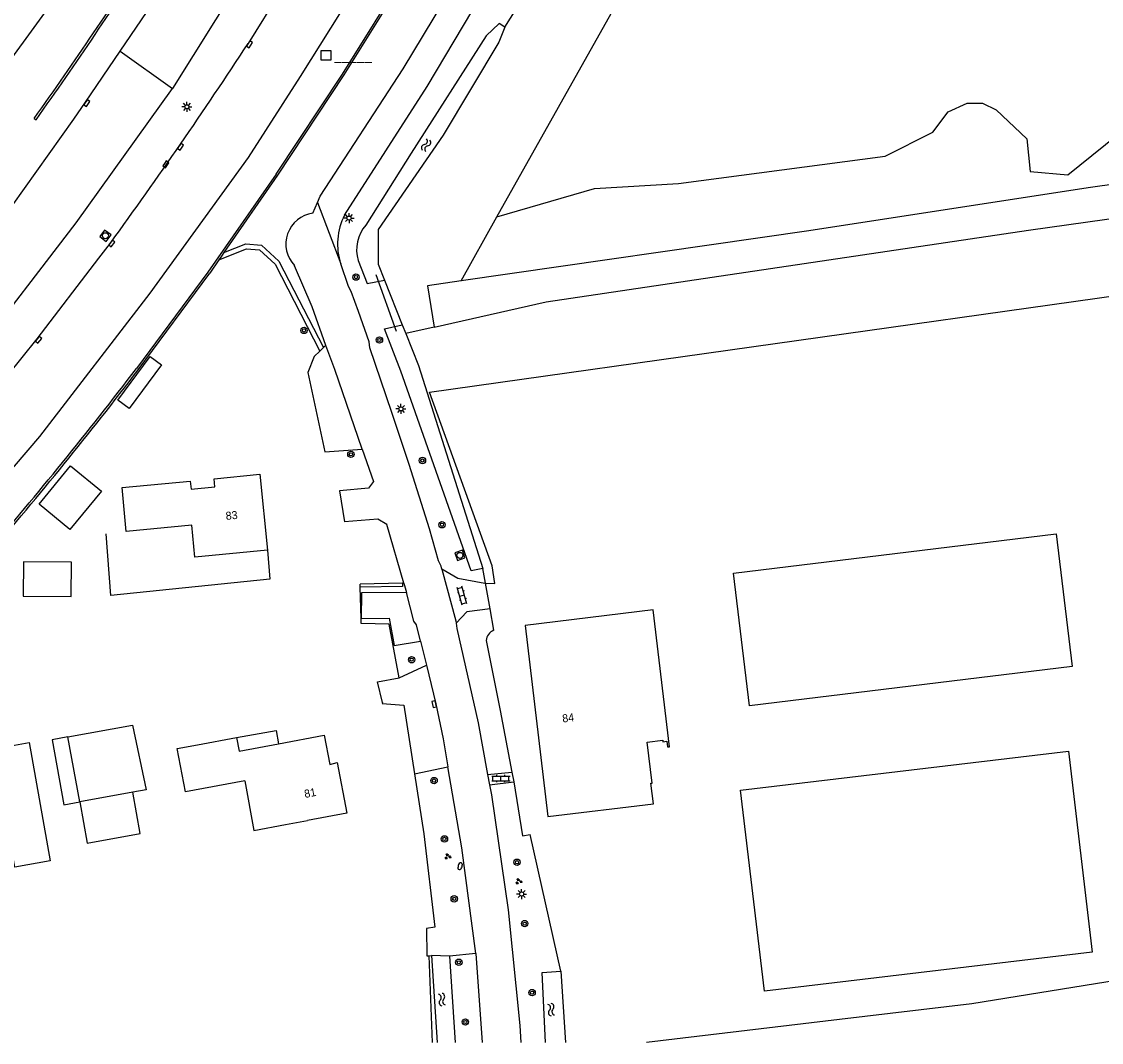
# Model space of a CAD drawing. Extents: x 125000 to 129004, y 397500 to 399008.
# Drawn here: x 125871.7 to 126006.6, y 397500 to 397627.5 of the extents above; entities that cross this region are included whole.
import ezdxf

# ---------------------------------------------------------------- set-up
doc = ezdxf.new("R2010")
doc.units = 0
for name, color, linetype in [('gg-afsc-erfafscheiding', 7, 'Continuous'), ('gg-afsc-geluidsscherm', 7, 'Continuous'), ('gg-afsc-hekwerk', 7, 'Continuous'), ('gg-anno-huisnummerreeks BGT', 7, 'Continuous'), ('gg-bbg-bijgebouw', 7, 'Continuous'), ('gg-bbg-gedigitaliseerde bebouwing', 7, 'Continuous'), ('gg-bbg-gedigitaliseerde bijgebouw', 7, 'Continuous'), ('gg-bbg-hoofdgebouw', 7, 'Continuous'), ('gg-bbg-luifel en loopbrug', 7, 'Continuous'), ('gg-knt-onverhard', 7, 'Continuous'), ('gg-knt-verharding', 7, 'Continuous'), ('gg-knt-verharding nz', 7, 'Continuous'), ('gg-kntw-bovenkant insteek waterloop', 7, 'Continuous'), ('gg-kwrk-duiker nz buis', 7, 'Continuous'), ('gg-kwrk-kunstwerk', 7, 'Continuous'), ('gt-bbg-plantopografie pand', 7, 'Continuous'), ('gt-grn-groengrens', 7, 'Continuous'), ('gt-grn-vlakafsluiter', 7, 'Continuous'), ('gt-grn-weggrens', 7, 'Continuous'), ('gt-symb-boom', 7, 'Continuous'), ('gt-symb-brandkraan', 7, 'Continuous'), ('gt-symb-groenvak', 7, 'Continuous'), ('gt-symb-hm paal', 7, 'Continuous'), ('gt-symb-klinker verharding', 7, 'Continuous'), ('gt-symb-kolk', 7, 'Continuous'), ('gt-symb-lichtmast', 7, 'Continuous'), ('gt-symb-rioolschacht', 7, 'Continuous'), ('gt-symb-watersymbool', 7, 'Continuous'), ('gx-grn-maaiveld', 7, 'Continuous')]:
    doc.layers.add(name, color=color, linetype=linetype)

# ---------------------------------------------------------------- blocks, each defined once
blk = doc.blocks.new('gt0-BOOM')
at = {"layer": 'gt-symb-boom'}
for radius in [0.4, 0.2]:
    blk.add_circle((0, 0), radius, dxfattribs=at)
blk = doc.blocks.new('gt0-WA')
at = {"layer": 'gt-symb-watersymbool'}
for centre, start, end in [((-0.32, 0.02), 28.0725, 151.9275), ((0.43, 0.42), 208.0725, 331.9275), ((-0.32, -0.43), 28.0725, 151.9275), ((0.43, -0.03), 208.0725, 331.9275)]:
    blk.add_arc(centre, 0.425, start, end, dxfattribs=at)
blk = doc.blocks.new('gt0-KL1')
at = {"layer": 'gt-symb-klinker verharding'}
for p, q in [((-1.15, 0.3), (1.15, 0.3)), ((-1, -0.3), (-1, 0.3)), ((-0.5, 0.3), (-0.5, 0.45)), ((0, -0.3), (0, 0.3)), ((0.5, 0.3), (0.5, 0.45)), ((1, -0.3), (1, 0.3)), ((-1.15, -0.3), (1.15, -0.3)), ((-0.5, -0.45), (-0.5, -0.3)), ((0.5, -0.45), (0.5, -0.3))]:
    blk.add_line(p, q, dxfattribs=at)
blk = doc.blocks.new('gt0-LMAST')
at = {"layer": 'gt-symb-lichtmast'}
for p, q in [((-0.18, 0.17), (-0.45, 0.44)), ((-0.01, 0.25), (-0.01, 0.62)), ((0.17, 0.17), (0.44, 0.44)), ((-0.26, 0), (-0.63, 0)), ((-0.18, -0.18), (-0.45, -0.45)), ((-0.01, -0.25), (-0.01, -0.63)), ((0.44, -0.45), (0.17, -0.18)), ((0.24, 0), (0.62, 0))]:
    blk.add_line(p, q, dxfattribs=at)
blk.add_circle((-0.01, 0), 0.25, dxfattribs=at)
blk = doc.blocks.new('gt0-GRVAK')
at = {"layer": 'gt-symb-groenvak'}
for p, q in [((-0.11, 0.19), (-0.23, 0.24)), ((-0.18, 0.15), (0.09, 0.15)), ((-0.09, 0.21), (-0.16, 0.32)), ((-0.05, 0.21), (-0.05, 0.39)), ((0, 0.21), (0.06, 0.32)), ((0.01, 0.19), (0.13, 0.24)), ((0.26, -0.05), (0.2, 0.06)), ((0.3, -0.05), (0.3, 0.13)), ((0.35, -0.05), (0.41, 0.06)), ((-0.24, -0.23), (-0.36, -0.18)), ((-0.32, -0.26), (-0.05, -0.26)), ((-0.23, -0.21), (-0.29, -0.09)), ((-0.18, -0.2), (-0.18, -0.02)), ((-0.14, -0.21), (-0.07, -0.09)), ((-0.12, -0.23), (0, -0.18)), ((0.24, -0.07), (0.12, -0.02)), ((0.17, -0.11), (0.44, -0.11)), ((0.37, -0.07), (0.49, -0.02))]:
    blk.add_line(p, q, dxfattribs=at)
blk = doc.blocks.new('gt0-BR')
at = {"layer": 'gt-symb-brandkraan'}
for centre, radius, start, end in [((-0.24, 0), 0.206, 107.5669, 252.4331), ((0.6, -2.66), 3, 106.892, 107.5669), ((0, -0.69), 0.938, 73.108, 106.892), ((-0.6, -2.66), 3, 72.4331, 73.108), ((0.24, 0), 0.206, 287.567, 72.4331), ((0.6, 2.66), 3, 252.4331, 253.108), ((0, 0.69), 0.938, 253.108, 286.8921), ((-0.6, 2.66), 3, 286.8921, 287.567)]:
    blk.add_arc(centre, radius, start, end, dxfattribs=at)
blk = doc.blocks.new('gt0-KOLK')
at = {"layer": 'gt-symb-kolk'}
blk.add_lwpolyline([(0, 0), (0.37, 0), (0.37, 0.4), (-0.38, 0.4), (-0.38, 0), (0, 0)], dxfattribs=at)
blk = doc.blocks.new('gt0-HMpaal')
at = {"layer": 'gt-symb-hm paal'}
blk.add_lwpolyline([(-0.6, 0.6), (0.6, 0.6), (0.6, -0.6), (-0.6, -0.6)], close=True, dxfattribs=at)
blk = doc.blocks.new('gt0-RS')
at = {"layer": 'gt-symb-rioolschacht'}
blk.add_lwpolyline([(-0.5, -0.5), (0.5, -0.5), (0.5, 0.5), (-0.5, 0.5)], close=True, dxfattribs=at)
blk.add_circle((0, 0), 0.375, dxfattribs=at)

msp = doc.modelspace()

# ---------------------------------------------------------------- linework, layer by layer
at = {"layer": 'gg-afsc-erfafscheiding'}
for points in [[(125860.37, 397605.46), (125867.29, 397618.68), (125878.83, 397634.5), (125884.89, 397642.75), (125889.59, 397650.36), (125895.8, 397652.97), (125896.33, 397653.98)], [(125902.39, 397561.51), (125902.67, 397557.86), (125882.8, 397555.82), (125882.23, 397563.55)], [(125916.75, 397542.47), (125916.74, 397542.36), (125919.43, 397542.12), (125920.78, 397533.56)], [(125920.78, 397533.56), (125921.95, 397526.07), (125923.31, 397514.41), (125922.25, 397514.21), (125922.32, 397510.8)]]:
    msp.add_lwpolyline(points, dxfattribs=at)
at = {"layer": 'gg-afsc-geluidsscherm'}
for p, q in [((125919.9, 397633.64), (125911.92, 397620.88)), ((125903.49, 397608.46), (125894.94, 397596.24)), ((125896.33, 397597.77), (125895.17, 397596.1)), ((125896.64, 397598.22), (125896.33, 397597.77)), ((125896.95, 397598.67), (125896.64, 397598.22)), ((125894.94, 397596.24), (125886.01, 397584.18)), ((125886.23, 397584.01), (125895.17, 397596.1))]:
    msp.add_line(p, q, dxfattribs=at)
for points in [[(125903.49, 397608.46), (125911.75, 397620.98), (125919.73, 397633.75), (125919.9, 397633.64)], [(125911.92, 397620.88), (125903.66, 397608.35), (125896.95, 397598.67)]]:
    msp.add_lwpolyline(points, dxfattribs=at)
for centre, radius, start, end in [((125501.32, 397877.52), 483.77, 319.1366, 322.6727), ((125499.58, 397878.93), 486.28, 319.1445, 322.6648)]:
    msp.add_arc(centre, radius, start, end, dxfattribs=at)
at = {"layer": 'gg-afsc-hekwerk'}
msp.add_line((125916.75, 397542.47), (125916.15, 397545.05), dxfattribs=at)
at = {"layer": 'gg-bbg-bijgebouw'}
for p, q in [((125878.93, 397530.04), (125877.44, 397538.16)), ((125885.56, 397531.26), (125878.93, 397530.04))]:
    msp.add_line(p, q, dxfattribs=at)
for points in [[(126000.95, 397563.52), (126002.96, 397546.95), (125962.65, 397542.05), (125960.63, 397558.63), (126000.95, 397563.52)], [(125877.44, 397538.16), (125885.51, 397539.63), (125887.21, 397531.56), (125885.56, 397531.26)]]:
    msp.add_lwpolyline(points, dxfattribs=at)
at = {"layer": 'gg-bbg-gedigitaliseerde bebouwing'}
msp.add_line((125952.65, 397536.94), (125950.59, 397554.06), dxfattribs=at)
at = {"layer": 'gg-bbg-gedigitaliseerde bijgebouw'}
for points in [[(125873.84, 397567.26), (125877.77, 397572.05), (125881.64, 397568.87), (125877.7, 397564.08), (125873.84, 397567.26)], [(125871.86, 397555.75), (125877.86, 397555.69), (125877.9, 397559.99), (125871.9, 397560.05), (125871.86, 397555.75)], [(125868.56, 397533.55), (125868, 397536.63), (125872.61, 397537.46), (125875.25, 397522.69), (125870.82, 397521.9), (125870.29, 397524.85), (125867.34, 397524.32), (125865.78, 397533.05), (125868.56, 397533.55)]]:
    msp.add_lwpolyline(points, dxfattribs=at)
at = {"layer": 'gg-bbg-hoofdgebouw'}
for p, q in [((125893.63, 397537.19), (125898.54, 397538.08)), ((125904.64, 397527.21), (125907.38, 397527.72))]:
    msp.add_line(p, q, dxfattribs=at)
for points in [[(125902.39, 397561.51), (125893.33, 397560.64), (125892.95, 397564.6), (125884.72, 397563.82), (125884.21, 397569.32), (125892.74, 397570.11), (125892.84, 397569.11), (125895.8, 397569.42), (125895.71, 397570.42), (125901.45, 397571), (125902.39, 397561.51)], [(125950.59, 397554.06), (125934.58, 397552.1), (125937.45, 397528.23), (125950.62, 397529.82), (125950.31, 397532.38), (125950.45, 397532.4), (125949.83, 397537.53), (125951.79, 397537.77), (125951.82, 397537.57), (125952.31, 397537.63), (125952.4, 397536.91), (125952.65, 397536.94)], [(125898.54, 397538.08), (125898.87, 397536.38), (125903.76, 397537.3)], [(125903.76, 397537.3), (125909.46, 397538.37), (125910.18, 397534.73), (125911.12, 397534.98), (125912.29, 397528.62), (125907.38, 397527.72)], [(125899.55, 397532.69), (125892.14, 397531.31), (125891.12, 397536.72), (125893.63, 397537.19)], [(125899.55, 397532.69), (125900.69, 397526.48), (125904.64, 397527.21)]]:
    msp.add_lwpolyline(points, dxfattribs=at)
at = {"layer": 'gg-bbg-luifel en loopbrug'}
for points in [[(125883.7, 397580.25), (125887.73, 397585.69), (125889.13, 397584.66), (125885.1, 397579.21), (125883.7, 397580.25)], [(125877.44, 397538.16), (125875.47, 397537.8), (125876.93, 397529.68), (125878.93, 397530.04)], [(125898.54, 397538.08), (125903.46, 397538.97), (125903.76, 397537.3)], [(125878.93, 397530.04), (125879.85, 397524.9), (125886.49, 397526.09), (125885.56, 397531.26)]]:
    msp.add_lwpolyline(points, dxfattribs=at)
at = {"layer": 'gg-knt-onverhard'}
for points in [[(126016.75, 397608.42), (126004.96, 397606.78), (125970.06, 397601.41), (125926.58, 397595.14)], [(125923.23, 397589.37), (125937.21, 397592.52), (125997.52, 397601.46), (126014.4, 397603.84)], [(125926.58, 397595.14), (125922.4, 397594.53), (125923.23, 397589.37)]]:
    msp.add_lwpolyline(points, dxfattribs=at)
at = {"layer": 'gg-knt-verharding'}
for p, q in [((125908.64, 397604.95), (125908.97, 397605.73)), ((125908.07, 397603.6), (125908.64, 397604.95)), ((125909.4, 397586.81), (125908.95, 397586.38)), ((125909.69, 397587.08), (125909.4, 397586.81)), ((125909.55, 397573.8), (125914.24, 397574.1)), ((125919.43, 397557.39), (125919.75, 397556.21)), ((125921.51, 397550.14), (125922.26, 397547.14)), ((125918.86, 397545.55), (125922.26, 397547.14)), ((125916.15, 397545.05), (125918.86, 397545.55)), ((125920.78, 397533.56), (125924.94, 397534.43)), ((125929.91, 397533.47), (125932.94, 397533.77)), ((125929.91, 397533.47), (125930.14, 397532.19)), ((125932.94, 397533.77), (125933.17, 397532.56)), ((125930.14, 397532.19), (125933.17, 397532.56)), ((125928.42, 397511.1), (125929.23, 397500))]:
    msp.add_line(p, q, dxfattribs=at)
for points in [[(125908.19, 397647.99), (125903.87, 397640.51), (125890.51, 397619.19)], [(125900.04, 397610.54), (125906.5, 397620.67), (125915.21, 397634.59), (125919.29, 397641.65)], [(125909.37, 397640.01), (125908.06, 397637.82), (125899.97, 397624.8)], [(125908.97, 397605.73), (125919.35, 397621.62), (125928.29, 397636.51)], [(125912.01, 397603.35), (125922.35, 397619.44), (125931.45, 397634.71)], [(125883.99, 397623.83), (125887.98, 397629.72), (125889.83, 397632.58)], [(125869.92, 397603.8), (125870.48, 397604.53), (125878.17, 397615.33), (125879.66, 397617.45), (125883.99, 397623.83)], [(125778.49, 397500), (125784.76, 397505.18), (125801.19, 397519.16), (125817.41, 397533.74), (125833, 397548.92), (125851.39, 397568.74), (125865.4, 397585.41), (125878.47, 397602.38), (125890.51, 397619.19)], [(125798.24, 397500), (125811.15, 397511.1), (125828.46, 397526.65), (125844.83, 397542.94), (125859.76, 397559.17), (125873.93, 397575.7), (125887.72, 397593.6), (125900.04, 397610.54)], [(125786.16, 397500), (125787.88, 397501.43), (125799.72, 397511.49), (125811.41, 397521.65), (125822.72, 397531.96), (125833.65, 397542.63), (125844.26, 397553.62), (125854.37, 397564.74), (125864.21, 397576.23), (125873.62, 397587.88), (125881.3, 397597.98), (125882.78, 397599.87)], [(125909.69, 397587.08), (125907.96, 397591.89), (125905.78, 397597.04)], [(125924.2, 397559.14), (125924.11, 397559.48), (125923.76, 397560.18), (125922.62, 397564.15), (125920.1, 397572.19), (125917.92, 397578.7), (125915.18, 397586.79), (125915.08, 397587.51), (125913.75, 397591.33), (125912.83, 397593.82), (125912.51, 397594.43), (125911.54, 397597.27)], [(125914.24, 397574.1), (125910.79, 397584.05), (125909.69, 397587.08)], [(125908.95, 397586.38), (125908.21, 397585.68), (125907.43, 397583.69)], [(125914.24, 397574.1), (125915.65, 397570.09), (125915.02, 397569.24), (125911.41, 397568.89)], [(125919.43, 397557.39), (125917.29, 397564.72), (125916.17, 397565.36), (125912.01, 397565.02)], [(125929.64, 397557.36), (125929.56, 397557.34), (125926.2, 397557.94), (125924.2, 397559.14)], [(125924.2, 397559.14), (125925.93, 397552.68), (125925.97, 397552.36)], [(125919.75, 397556.21), (125914.14, 397556.15), (125914.08, 397552.98)], [(125921.51, 397550.14), (125921, 397552.18), (125920.68, 397552.62), (125919.75, 397556.21)], [(125914.08, 397552.98), (125917.62, 397553.01), (125918.22, 397549.57), (125921.51, 397550.14)], [(125930.21, 397554.16), (125927.31, 397553.81), (125925.97, 397552.36)], [(125925.97, 397552.36), (125926.05, 397551.71), (125928.73, 397539.91), (125929.91, 397533.47)], [(125922.26, 397547.14), (125923.42, 397542.3), (125924.34, 397537.94), (125924.94, 397534.43)], [(125928.42, 397511.1), (125926.68, 397524.3), (125924.94, 397534.43)], [(125930.14, 397532.19), (125930.37, 397530.92), (125932.48, 397516.56), (125933.92, 397502.12), (125934.05, 397500)]]:
    msp.add_lwpolyline(points, dxfattribs=at)
for centre, radius, start, end in [((125390.83, 397957.36), 608.12, 323.99413, 326.84814), ((125908.59, 397599.74), 3.9, 97.7284, 223.7468), ((125919.18, 397599.73), 8.03, 153.2176, 197.8698)]:
    msp.add_arc(centre, radius, start, end, dxfattribs=at)
at = {"layer": 'gg-knt-verharding nz'}
msp.add_line((125908.64, 397604.95), (125911.54, 397597.27), dxfattribs=at)
at = {"layer": 'gg-kntw-bovenkant insteek waterloop'}
for p, q in [((125919.24, 397589.64), (125919.67, 397588.57)), ((125925.12, 397510.78), (125922.91, 397510.86)), ((125922.91, 397510.86), (125923.61, 397500)), ((125925.12, 397510.78), (125925.83, 397500))]:
    msp.add_line(p, q, dxfattribs=at)
for points in [[(125932.07, 397626.84), (125931.33, 397627.3), (125929.73, 397625.76), (125920.34, 397611.08), (125914.7, 397602.09)], [(125932.07, 397626.84), (125931.32, 397624.98), (125924.33, 397613.34), (125916.23, 397601.56), (125916.21, 397597.23), (125917, 397595.23)], [(125913.73, 397597.7), (125914.84, 397594.82), (125917, 397595.23)], [(125929.32, 397559.19), (125927.83, 397558.9), (125919.05, 397583.86), (125917.02, 397589.13), (125919.24, 397589.64)], [(125919.67, 397588.57), (125921.26, 397584.58), (125929.32, 397559.19)], [(125937.15, 397500), (125936.74, 397508.73), (125939.05, 397508.9)]]:
    msp.add_lwpolyline(points, dxfattribs=at)
msp.add_arc((125918.16, 397599.03), 4.63, 138.4944, 196.636, dxfattribs=at)
at = {"layer": 'gg-kwrk-duiker nz buis'}
msp.add_line((125915.92, 397595.94), (125918.49, 397588.87), dxfattribs=at)
at = {"layer": 'gg-kwrk-kunstwerk'}
msp.add_line((125873.24, 397615.42), (125873.47, 397615.28), dxfattribs=at)
for centre, radius, start, end in [((125484.76, 397892.66), 477.26, 324.4861, 327.6126), ((125483.79, 397893.33), 478.71, 324.4902, 327.5865)]:
    msp.add_arc(centre, radius, start, end, dxfattribs=at)
at = {"layer": 'gt-bbg-plantopografie pand'}
msp.add_lwpolyline([(125961.51, 397531.52), (126002.49, 397536.39), (126005.48, 397511.26), (125964.5, 397506.39), (125961.51, 397531.52)], dxfattribs=at)
at = {"layer": 'gt-grn-groengrens'}
for p, q in [((125931.07, 397603.13), (125958.7, 397652.38)), ((125932.07, 397626.84), (125934.45, 397630.64)), ((125926.58, 397595.14), (125931.07, 397603.13)), ((125917, 397595.23), (125919.24, 397589.64)), ((125923.23, 397589.37), (125919.67, 397588.57)), ((125929.64, 397557.36), (125929.32, 397559.19)), ((125919.25, 397557.39), (125913.96, 397557.24)), ((125914.08, 397552.98), (125913.97, 397556.88)), ((125930.69, 397551.49), (125930.21, 397554.16)), ((125939.05, 397508.9), (125935.21, 397525.99)), ((125928.42, 397511.1), (125925.12, 397510.78)), ((125922.32, 397510.8), (125922.56, 397510.83)), ((125922.56, 397510.83), (125922.91, 397510.86)), ((125922.56, 397510.83), (125922.98, 397500))]:
    msp.add_line(p, q, dxfattribs=at)
for points in [[(125931.07, 397603.13), (125943.28, 397606.67), (125953.74, 397607.31), (125979.58, 397610.73), (125985.56, 397613.72), (125987.48, 397616.28), (125989.83, 397617.35), (125991.75, 397617.35), (125993.46, 397616.5), (125997.3, 397612.87), (125997.73, 397608.81), (126002.43, 397608.38), (126010.12, 397614.58), (126012.04, 397615.43), (126021.11, 397616.94)], [(125896.33, 397597.77), (125899.77, 397599.16), (125901.39, 397599.03), (125903.34, 397597.24), (125908.95, 397586.38)], [(125896.95, 397598.67), (125899.68, 397599.77), (125901.64, 397599.61), (125903.82, 397597.61), (125909.4, 397586.81)], [(125929.64, 397557.36), (125930.79, 397557.32), (125930.48, 397559.56), (125922.63, 397581.22), (126009.05, 397593.39)], [(125919.25, 397557.39), (125919.26, 397556.96), (125913.97, 397556.88)], [(125918.86, 397545.55), (125917.6, 397552.26), (125914.1, 397552.35), (125914.08, 397552.98)], [(125929.72, 397550.2), (125931.47, 397541.48), (125932.94, 397533.77)], [(125933.17, 397532.56), (125934.28, 397525.82), (125935.21, 397525.99)]]:
    msp.add_lwpolyline(points, dxfattribs=at)
msp.add_arc((125931.21, 397550.09), 1.49, 110.7494, 175.7534, dxfattribs=at)
at = {"layer": 'gt-grn-vlakafsluiter'}
for p, q in [((125907.43, 397583.69), (125909.55, 397573.8)), ((125911.41, 397568.89), (125912.01, 397565.02)), ((125913.97, 397556.88), (125913.96, 397557.24)), ((125919.25, 397557.39), (125919.43, 397557.39))]:
    msp.add_line(p, q, dxfattribs=at)
at = {"layer": 'gt-grn-weggrens'}
for p, q in [((125883.99, 397623.83), (125890.51, 397619.19)), ((125930.21, 397554.16), (125929.64, 397557.36))]:
    msp.add_line(p, q, dxfattribs=at)
at = {"layer": 'gx-grn-maaiveld'}
msp.add_line((125939.05, 397508.9), (125939.64, 397500), dxfattribs=at)
msp.add_lwpolyline([(126050.48, 397520.76), (126051.72, 397514.59), (126020.09, 397509.71), (126008.7, 397507.76), (125990.41, 397504.83), (125973.9, 397502.88), (125949.75, 397500)], dxfattribs=at)

# ---------------------------------------------------------------- block references
at = {"layer": 'gt-symb-boom'}
for p in [(125913.45, 397595.61), (125906.96, 397588.95), (125916.38, 397587.76), (125912.82, 397573.47), (125921.76, 397572.7), (125924.2, 397564.67), (125920.41, 397547.81), (125923.21, 397532.71), (125924.51, 397525.42), (125933.58, 397522.51), (125925.73, 397517.94), (125934.54, 397514.84), (125926.31, 397510.01), (125935.46, 397506.22), (125927.12, 397502.55)]:
    msp.add_blockref('gt0-BOOM', p, dxfattribs=at)
at = {"layer": 'gt-symb-brandkraan', "rotation": 73.92082762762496}
msp.add_blockref('gt0-BR', (125926.47, 397522.02), dxfattribs=at)
at = {"layer": 'gt-symb-groenvak'}
for p in [(125924.91, 397523.22), (125933.79, 397520.11)]:
    msp.add_blockref('gt0-GRVAK', p, dxfattribs=at)
at = {"layer": 'gt-symb-hm paal'}
msp.add_blockref('gt0-HMpaal', (125909.69, 397623.32), dxfattribs=at)
at = {"layer": 'gt-symb-klinker verharding', "rotation": 105.91389307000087}
msp.add_blockref('gt0-KL1', (125926.69, 397555.8), dxfattribs=at)
at = {"layer": 'gt-symb-klinker verharding'}
msp.add_blockref('gt0-KL1', (125931.57, 397532.96), dxfattribs=at)
at = {"layer": 'gt-symb-kolk'}
for p, rotation in [((125899.97, 397624.8), -121.8633844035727), ((125879.66, 397617.45), -125.02487327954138), ((125891.37, 397612), -124.6032843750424), ((125889.52, 397609.81), -124.27826657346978), ((125882.78, 397599.92), -127.23665897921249), ((125873.62, 397587.88), -128.91039737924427), ((125923.42, 397542.3), 102.00670830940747)]:
    msp.add_blockref('gt0-KOLK', p, dxfattribs=dict(at, rotation=rotation))
at = {"layer": 'gt-symb-lichtmast'}
for p in [(125892.33, 397616.89), (125912.59, 397602.99), (125919.08, 397579.15), (125934.16, 397518.54)]:
    msp.add_blockref('gt0-LMAST', p, dxfattribs=at)
at = {"layer": 'gt-symb-rioolschacht'}
for p, rotation in [((125882.14, 397600.78), -126.13684490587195), ((125926.44, 397560.85), -71.45633066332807)]:
    msp.add_blockref('gt0-RS', p, dxfattribs=dict(at, rotation=rotation))
at = {"layer": 'gt-symb-watersymbool'}
for p, rotation in [((125922.24, 397612.14), -111.84397692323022), ((125924.19, 397505.4), -74.44827510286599), ((125937.84, 397504.14), -74.44827510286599)]:
    msp.add_blockref('gt0-WA', p, dxfattribs=dict(at, rotation=rotation))

# ---------------------------------------------------------------- texts
at = {"layer": 'gg-anno-huisnummerreeks BGT'}
for s, rotation, p in [('83', 5.7, (125897.22, 397565.27)), ('84', 6.8, (125939.29, 397539.96)), ('81', 10.4, (125907.08, 397530.54))]:
    msp.add_text(s, height=1, rotation=rotation, dxfattribs=at).set_placement(p)
at = {"layer": 'gt-symb-hm paal'}
msp.add_text('_____', height=1.25, dxfattribs=at).set_placement((125910.77, 397622.72))

doc.saveas('drawing.dxf')
